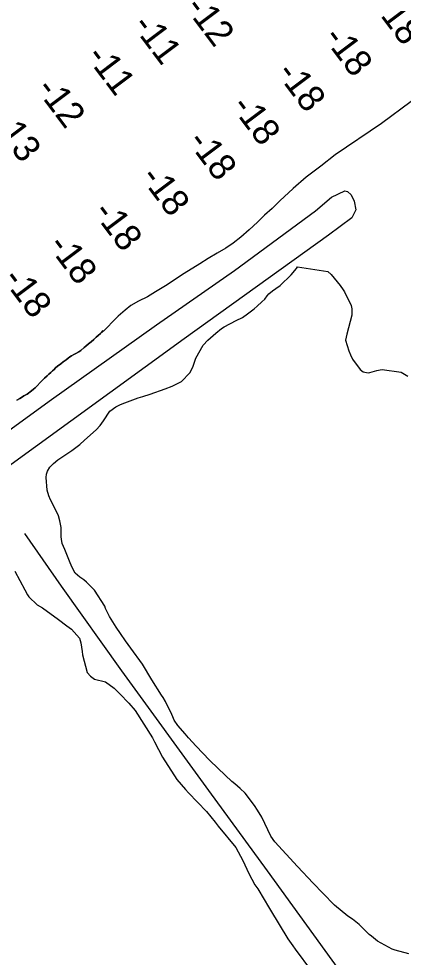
# Model space of a CAD drawing. Extents: x 3683613 to 3738215, y 469626 to 495384.
# Drawn here: x 3694543 to 3695195, y 490673 to 492263 of the extents above; entities that cross this region are included whole.
import ezdxf

# ---------------------------------------------------------------- set-up
doc = ezdxf.new("R2010")
doc.units = 0
for name, color, linetype in [('V-LEVE-TOET', 7, 'Continuous'), ('V-RIVR-JETY', 7, 'Continuous'), ('V-SITE-VEGE', 7, 'Continuous'), ('V-TOPO-SHOR', 7, 'Continuous'), ('V-TOPO-SPOT', 7, 'Continuous')]:
    doc.layers.add(name, color=color, linetype=linetype)

msp = doc.modelspace()

# ---------------------------------------------------------------- linework, layer by layer
at = {"layer": 'V-LEVE-TOET'}
msp.add_lwpolyline([(3692742.2, 490254.9), (3693119.2, 490531), (3693505.2, 490808.5), (3693831.6, 491054.9), (3694164.5, 491302.4), (3694594.4, 491615), (3694776.6, 491744.1), (3694908.8, 491836.2), (3695045.7, 491937.3), (3695073, 491960.6), (3695095.4, 491971.2), (3695099.9, 491970), (3695106.2, 491964.6), (3695111.3, 491953.8), (3695114, 491939.2), (3695107.6, 491925.6), (3695067.8, 491896.4), (3694823.2, 491720.7), (3694504.8, 491489.9), (3694223, 491282.1), (3693783.2, 490953.5), (3693425, 490687.1), (3693111.9, 490453.6), (3692756, 490200.1)], dxfattribs=at)
at = {"layer": 'V-RIVR-JETY'}
msp.add_lwpolyline([(3694539.6, 491616.6), (3694544.7, 491619.6), (3694547.5, 491621.4), (3694551.7, 491623.8), (3694557.2, 491627.1), (3694564.4, 491632.5), (3694568.3, 491635.5), (3694571, 491637.8), (3694573.8, 491640.4), (3694579.9, 491647.1), (3694583.7, 491651.1), (3694586.7, 491654.2), (3694591, 491658), (3694594, 491661), (3694597.2, 491663.6), (3694600.2, 491666.2), (3694602.8, 491668.5), (3694605.5, 491671.3), (3694608.8, 491674.3), (3694614.1, 491678.5), (3694618.3, 491681.5), (3694623.4, 491685.3), (3694626.9, 491687.9), (3694629.6, 491689.9), (3694632.4, 491691.7), (3694636.6, 491694.1), (3694639.8, 491695.5), (3694645.1, 491698.4), (3694648.5, 491700.8), (3694654, 491705.7), (3694656.8, 491708.1), (3694661.3, 491711.9), (3694665.6, 491715.7), (3694670, 491719.5), (3694674.5, 491723.2), (3694677.7, 491726.2), (3694681.4, 491729.4), (3694683.5, 491731.6), (3694685.5, 491734.1), (3694686.9, 491733.7)], dxfattribs=at)
at = {"layer": 'V-SITE-VEGE'}
for points in [[(3694930.9, 491762.7), (3694942, 491771.3), (3694947, 491775.9), (3694955.2, 491783.3), (3694959.8, 491788), (3694964, 491793.5), (3694966.9, 491796.6), (3694973, 491802.1), (3694978.8, 491805.9), (3694985.8, 491810.9), (3695004.4, 491828.9), (3695013.9, 491839.8), (3695015.6, 491842.6), (3695066.8, 491834.7)], [(3695066.8, 491834.7), (3695072.3, 491829.3), (3695087.4, 491811.2), (3695092.8, 491803.8), (3695095.1, 491800.1), (3695106.5, 491777.2), (3695107.6, 491771.6), (3695107.2, 491760.7), (3695099, 491728.4), (3695096.7, 491718.1), (3695102.2, 491700.2), (3695105.2, 491693.3), (3695108.7, 491686.4), (3695121.4, 491668.7), (3695126.5, 491664.9), (3695134.9, 491663.1), (3695137.7, 491663.4), (3695149.5, 491667.1), (3695155.5, 491668.1), (3695158.8, 491668.4), (3695191.2, 491664.2), (3695202.2, 491657.1)], [(3695203.8, 490678.6), (3695181.1, 490684.9), (3695176, 490686.7), (3695151, 490700.3), (3695140.8, 490708.6), (3695136.9, 490711.5), (3695120.1, 490728.5), (3695108.3, 490737.7), (3695100.9, 490742.7), (3695078.1, 490761.1), (3695058.2, 490781.4), (3695041.8, 490798.7), (3695015.4, 490826.8), (3694976.8, 490868.6), (3694970.3, 490878.4), (3694955.1, 490910.2), (3694947.8, 490922.1), (3694942.5, 490930.3), (3694926.6, 490950.8), (3694918, 490959.1), (3694909.4, 490966.6), (3694904.3, 490970.8), (3694880.8, 490992.7), (3694866.4, 491006.8), (3694843.8, 491030.4), (3694830.5, 491044.9), (3694825.1, 491051.4), (3694812.7, 491065.5), (3694806.5, 491074.9), (3694803.9, 491080.6), (3694802.4, 491084.3), (3694791.8, 491106.3), (3694787.5, 491113.2), (3694784.9, 491117.3), (3694768.7, 491143.1), (3694752.6, 491169.3), (3694733, 491196.4), (3694724.1, 491209.1), (3694715.2, 491221.4), (3694707.9, 491232.1), (3694699.8, 491245.6), (3694696.8, 491250.5), (3694690.3, 491263.6), (3694688.8, 491267.6), (3694671.2, 491294.7), (3694657.9, 491308.7), (3694653.6, 491312.1), (3694646.5, 491317.1), (3694638.7, 491323.8), (3694633.7, 491333.1), (3694630.3, 491341.3), (3694626.6, 491349.8), (3694621, 491363.7), (3694616.9, 491374.2), (3694615.5, 491381.5), (3694615.2, 491385.1), (3694614.8, 491400.8), (3694612.8, 491412.5), (3694610.2, 491420.6), (3694604.5, 491432.9), (3694596.9, 491447.9), (3694593.9, 491454.9), (3694591.4, 491464.2), (3694589.6, 491485.5), (3694590.2, 491491.5), (3694591.9, 491496.7), (3694595.8, 491503), (3694602, 491509.7), (3694609.4, 491515.9), (3694632.8, 491531.7), (3694646.3, 491541.7), (3694654.6, 491548.7), (3694674.4, 491566.6), (3694681, 491574), (3694686.5, 491581.9), (3694697.4, 491598.1), (3694707.7, 491605.4), (3694715.4, 491609.2), (3694722.7, 491612.2), (3694745.5, 491620.4), (3694753.2, 491622.9), (3694765.8, 491626.6), (3694791.3, 491635.9), (3694803.1, 491640.3), (3694818.6, 491648.3), (3694833.1, 491663.2), (3694838.2, 491672.7), (3694843.1, 491687.8), (3694855.8, 491709.9), (3694863.7, 491718.1), (3694876.9, 491730.2), (3694886.4, 491737.9), (3694891.3, 491741), (3694911.7, 491751.7), (3694921.9, 491756.6), (3694930.9, 491762.7)], [(3694536.3, 491326.8), (3694553.1, 491295.7), (3694558, 491286.8), (3694559.9, 491283.5), (3694574.4, 491269.8), (3694583.1, 491264.7), (3694610.6, 491245), (3694624.4, 491234.6), (3694632.6, 491228.7), (3694645.9, 491213.4), (3694648, 491205.8), (3694650.4, 491190.8), (3694651.1, 491185.6), (3694659, 491155.2), (3694664.5, 491149.4), (3694671.5, 491144), (3694690.3, 491139.4), (3694704.8, 491128.9), (3694709.5, 491124.4), (3694714.2, 491119), (3694729.4, 491103.7), (3694740.3, 491090.9), (3694769.9, 491044.6), (3694773.3, 491037.7), (3694786.6, 491012), (3694810.8, 490973.9), (3694825.5, 490957), (3694830.6, 490951.6), (3694861, 490920.2), (3694875.7, 490901.7), (3694880.8, 490895.1), (3694910.6, 490858.9), (3694922.8, 490837.2), (3694933, 490814.8), (3694942.9, 490796), (3694947.9, 490788.7), (3694951.8, 490783.3), (3694955.6, 490776.8), (3694969.4, 490752.7), (3694998.9, 490704.4), (3695007.4, 490692.5), (3695011.2, 490686.7), (3695039, 490649.7)]]:
    msp.add_lwpolyline(points, dxfattribs=at)
at = {"layer": 'V-TOPO-SHOR'}
for points in [[(3695207.7, 492122.8), (3695157.8, 492085.6), (3695079.4, 492032.5), (3695054.7, 492013), (3695030.1, 491994.6), (3695008.2, 491975.5), (3694985.4, 491954.4), (3694972.3, 491941.6), (3694959.6, 491930.2), (3694947.6, 491918.2), (3694933.3, 491905.1), (3694919.4, 491892.9), (3694906.1, 491882.6), (3694894, 491874)], [(3694894, 491874), (3694879.5, 491865.7), (3694864, 491856.4), (3694849.8, 491847.9), (3694823.6, 491831.5), (3694791.5, 491810.5), (3694774.8, 491800.1), (3694761.2, 491791.8), (3694745.8, 491784.4), (3694733.2, 491777.2), (3694723.4, 491769.3), (3694711.7, 491758.9), (3694701.4, 491748.7), (3694694.2, 491741.1), (3694686.9, 491733.7)], [(3694539.6, 491616.6), (3694544.7, 491619.6), (3694547.5, 491621.4), (3694551.7, 491623.8), (3694557.2, 491627.1), (3694564.4, 491632.5), (3694568.3, 491635.5), (3694571, 491637.8), (3694573.8, 491640.4), (3694579.9, 491647.1), (3694583.7, 491651.1), (3694586.7, 491654.2), (3694591, 491658), (3694594, 491661), (3694597.2, 491663.6), (3694600.2, 491666.2), (3694602.8, 491668.5), (3694605.5, 491671.3), (3694608.8, 491674.3), (3694614.1, 491678.5), (3694618.3, 491681.5), (3694623.4, 491685.3), (3694626.9, 491687.9), (3694629.6, 491689.9), (3694632.4, 491691.7), (3694636.6, 491694.1), (3694639.8, 491695.5), (3694645.1, 491698.4), (3694648.5, 491700.8), (3694654, 491705.7), (3694656.8, 491708.1), (3694661.3, 491711.9), (3694665.6, 491715.7), (3694670, 491719.5), (3694674.5, 491723.2), (3694677.7, 491726.2), (3694681.4, 491729.4), (3694683.5, 491731.6), (3694685.5, 491734.1), (3694686.9, 491733.7)], [(3694686.9, 491733.7), (3694685.5, 491734.1), (3694683.5, 491731.6), (3694681.4, 491729.4), (3694677.7, 491726.2), (3694674.5, 491723.2), (3694670, 491719.5), (3694665.6, 491715.7), (3694661.3, 491711.9), (3694656.8, 491708.1), (3694654, 491705.7), (3694648.5, 491700.8), (3694645.1, 491698.4), (3694639.8, 491695.5), (3694636.6, 491694.1), (3694632.4, 491691.7), (3694629.6, 491689.9), (3694626.9, 491687.9), (3694623.4, 491685.3), (3694618.3, 491681.5), (3694614.1, 491678.5), (3694608.8, 491674.3), (3694605.5, 491671.3), (3694602.8, 491668.5), (3694600.2, 491666.2), (3694597.2, 491663.6), (3694594, 491661), (3694591, 491658), (3694586.7, 491654.2), (3694583.7, 491651.1), (3694579.9, 491647.1), (3694573.8, 491640.4), (3694571, 491637.8), (3694568.3, 491635.5), (3694564.4, 491632.5), (3694557.2, 491627.1), (3694551.7, 491623.8), (3694547.5, 491621.4), (3694544.7, 491619.6)], [(3694544.7, 491619.6), (3694539.6, 491616.6)], [(3694552.6, 491391), (3694614.9, 491301.6), (3694717, 491158.4), (3694864.3, 490955.5), (3694963.9, 490819.2), (3695085.3, 490651.9), (3695137.9, 490577.6), (3695146.1, 490570.4)]]:
    msp.add_lwpolyline(points, dxfattribs=at)

# ---------------------------------------------------------------- texts
at = {"layer": 'V-TOPO-SPOT'}
for s, p in [('-12', (3694823.4, 492281.7)), ('-18', (3695142.8, 492284.2)), ('-11', (3694734.1, 492251.1)), ('-18', (3695057.8, 492230.7)), ('-11', (3694655.7, 492198.8)), ('-18', (3694978.3, 492170.7)), ('-12', (3694570.9, 492143.6)), ('-18', (3694901.7, 492114)), ('-13', (3694496.1, 492085.7)), ('-18', (3694827.6, 492054.6)), ('-18', (3694747.9, 491994.1)), ('-18', (3694667.5, 491934.9)), ('-18', (3694591, 491878.4)), ('-18', (3694514.3, 491821.7))]:
    msp.add_text(s, height=45, rotation=306.9347, dxfattribs=at).set_placement(p)

doc.saveas('drawing.dxf')
